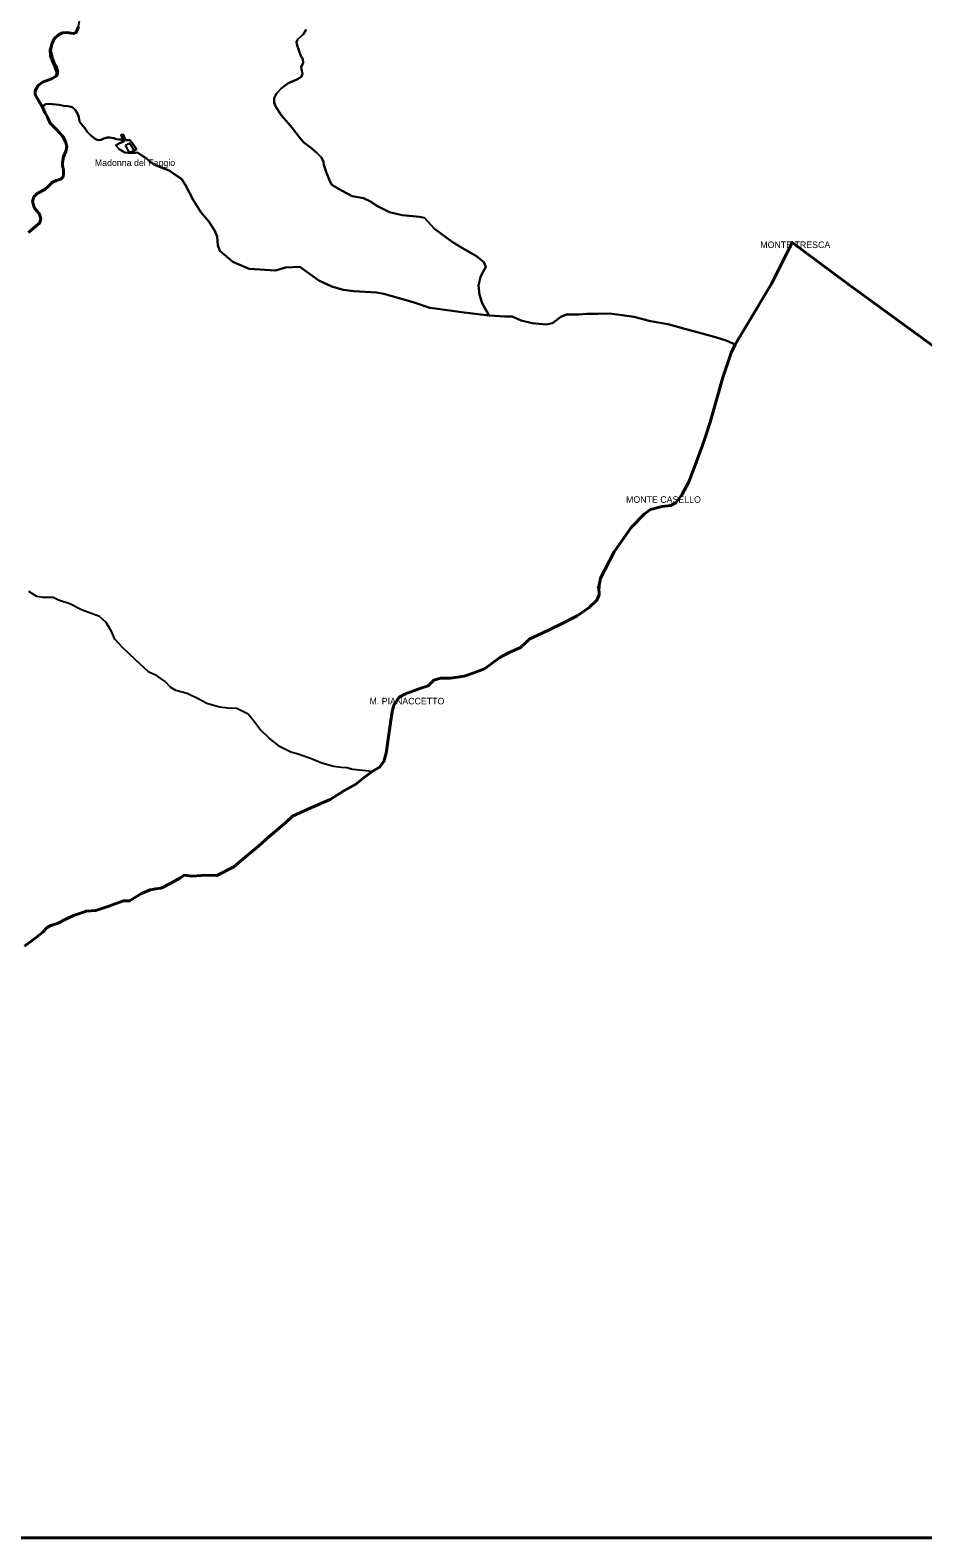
# Model space of a CAD drawing. Extents: x 645880 to 658994, y 884400 to 894744.
# Drawn here: x 651612 to 653916, y 884400 to 888292 of the extents above; entities that cross this region are included whole.
import ezdxf
from ezdxf.enums import TextEntityAlignment as Align

# ---------------------------------------------------------------- set-up
doc = ezdxf.new("R2010")
doc.units = 0
doc.header["$LTSCALE"] = 10
doc.header["$PDMODE"] = 32
doc.header["$PDSIZE"] = 5
for name, color, linetype, lineweight in [('18', 7, 'Continuous', 25), ('2', 7, 'Continuous', 25), ('59', 7, 'Continuous', 40), ('63', 7, 'Continuous', 35)]:
    doc.layers.add(name, color=color, linetype=linetype, lineweight=lineweight)
doc.layers.add('60', color=7, linetype='Continuous')

msp = doc.modelspace()

# ---------------------------------------------------------------- linework, layer by layer
at = {"layer": '18'}
for points in [[(651679.17, 888183.52), (651674.63, 888197.73), (651669.19, 888209.23), (651662.85, 888224.95), (651661.94, 888240.68), (651667.38, 888257.32), (651673.26, 888269.69), (651684.33, 888280.01), (651694.98, 888284.97), (651706.48, 888285.38), (651723.65, 888283.39), (651732.07, 888285.72), (651736.28, 888300.67), (651739, 888316.08), (651740.59, 888333.89), (651738.85, 888344.08), (651731.18, 888352.01), (651709.04, 888367.7), (651694.13, 888390.42), (651681.78, 888411.08), (651676.25, 888430.49), (651676.86, 888459.65)], [(653430.75, 887480.32), (653408.36, 887490.26), (653383.29, 887498.33), (653345.76, 887508.94), (653310.84, 887517.91), (653257, 887532.38), (653212.48, 887540.2), (653169.23, 887552.1), (653133.87, 887556.72), (653107.94, 887560.26), (653077.67, 887559.48), (653048, 887559.68), (653026.97, 887557.91), (653011.45, 887557.89), (652995.93, 887557.49), (652981.58, 887551.4), (652959.57, 887535.08), (652943.26, 887532.32), (652907.3, 887535.67), (652878.61, 887541.96), (652855.62, 887552.58), (652836.36, 887552.38), (652796.08, 887555.13), (652787.7, 887570.02), (652777.81, 887586.99), (652771.32, 887608.23), (652768.96, 887632.22), (652773.68, 887655.03), (652782.52, 887670.96), (652787.63, 887680.79), (652782.52, 887692.39), (652763.26, 887708.71), (652727.3, 887729.16), (652700.82, 887745.68), (652654.8, 887778.72), (652629.45, 887806.84), (652616.48, 887809.59), (652571.85, 887813.8), (652538.72, 887821.86), (652508.27, 887837.1), (652488.56, 887850.54), (652471.55, 887857.71), (652442.96, 887862.87), (652429.79, 887869.75), (652407.06, 887881.91), (652389.71, 887893.34), (652382.88, 887906.11), (652376.55, 887923.23), (652369.44, 887943.75), (652368.49, 887952.13), (652363.77, 887963.15), (652351.55, 887975.33), (652334.07, 887989.32), (652318.19, 888001.49), (652307.18, 888013.88), (652287.44, 888039.34), (652277.82, 888051.58), (652260.34, 888071.7), (652245.48, 888093.57), (652241.11, 888104.94), (652240.96, 888116.34), (652247.25, 888128.33), (652260.62, 888142.1), (652279.09, 888155.67), (652290.68, 888159.8), (652303.65, 888165.89), (652311.51, 888172.18), (652314.66, 888179.85), (652312.69, 888186.93), (652310.92, 888196.37), (652316.03, 888207.19), (652315.13, 888216.88), (652309.29, 888227.39), (652299.92, 888255.17), (652299.33, 888261.86), (652302.28, 888268.74), (652317.21, 888281.72), (652323.7, 888293.52)], [(652323.7, 888293.52), (652317.21, 888281.72), (652302.28, 888268.74), (652299.33, 888261.86), (652299.92, 888255.17), (652309.29, 888227.39), (652315.13, 888216.88), (652316.03, 888207.19), (652310.92, 888196.37), (652312.69, 888186.93), (652314.66, 888179.85), (652311.51, 888172.18), (652303.65, 888165.89), (652290.68, 888159.8), (652279.09, 888155.67), (652260.62, 888142.1), (652247.25, 888128.33), (652240.96, 888116.34), (652241.11, 888104.94)], [(651853.69, 888004.63), (651847.22, 888009.53), (651840.4, 888009.53), (651834.67, 888010.08), (651826.76, 888013.08), (651816.94, 888014.99), (651810.12, 888014.45), (651801.67, 888012.26), (651795.12, 888008.71), (651788.85, 888007.62), (651785.03, 888008.17), (651780.39, 888010.08), (651767.03, 888020.45), (651759.39, 888028.09), (651752.57, 888038.74), (651744.12, 888048.84), (651738.66, 888056.21), (651736.75, 888066.86), (651733.48, 888076.41), (651727.48, 888085.97), (651722.57, 888091.15), (651717.66, 888093.88), (651708.93, 888095.79), (651697.74, 888096.61), (651686.01, 888098.52), (651668.56, 888100.43), (651658.46, 888101.8), (651652.19, 888100.44), (651645.1, 888096.35), (651640.78, 888095.21), (651635.03, 888106.1), (651624.16, 888124.57), (651623.65, 888127), (651624.76, 888139.66), (651632.32, 888150.55), (651643.01, 888157.31), (651666.43, 888166.4), (651677.05, 888172.63), (651679.47, 888176.86), (651679.17, 888183.52)], [(651640.78, 888095.21), (651645.1, 888096.35), (651652.19, 888100.44), (651658.46, 888101.8), (651668.56, 888100.43), (651686.01, 888098.52), (651697.74, 888096.61), (651708.93, 888095.79), (651717.66, 888093.88), (651722.57, 888091.15), (651727.48, 888085.97), (651733.48, 888076.41), (651736.75, 888066.86), (651738.66, 888056.21), (651744.12, 888048.84), (651752.57, 888038.74), (651759.39, 888028.09), (651767.03, 888020.45), (651780.39, 888010.08), (651785.03, 888008.17), (651788.85, 888007.62), (651795.12, 888008.71), (651801.67, 888012.26), (651810.12, 888014.45), (651816.94, 888014.99), (651826.76, 888013.08), (651834.67, 888010.08), (651840.4, 888009.53), (651847.22, 888009.53), (651853.69, 888004.63)], [(651649.85, 888079.07), (651643.12, 888091.05), (651640.78, 888095.21)], [(651680.1, 888034.48), (651662.24, 888051.05), (651657.1, 888062.54), (651649.85, 888079.07)], [(652241.11, 888104.94), (652245.48, 888093.57), (652260.34, 888071.7), (652277.82, 888051.58), (652287.44, 888039.34), (652307.18, 888013.88), (652318.19, 888001.49), (652334.07, 887989.32), (652351.55, 887975.33), (652363.77, 887963.15), (652368.49, 887952.13), (652369.44, 887943.75), (652376.55, 887923.23), (652382.88, 887906.11), (652389.71, 887893.34), (652407.06, 887881.91), (652429.79, 887869.75), (652442.96, 887862.87), (652471.55, 887857.71), (652488.56, 887850.54), (652508.27, 887837.1), (652538.72, 887821.86), (652571.85, 887813.8), (652616.48, 887809.59), (652629.45, 887806.84), (652654.8, 887778.72), (652700.82, 887745.68), (652727.3, 887729.16), (652763.26, 887708.71), (652782.52, 887692.39), (652787.63, 887680.79), (652782.52, 887670.96), (652773.68, 887655.03), (652768.96, 887632.22), (652771.32, 887608.23), (652777.81, 887586.99), (652787.7, 887570.02), (652796.08, 887555.13)], [(651695.83, 888017.52), (651680.1, 888034.48), (651680.08, 888034.46)], [(651697.99, 887931.05), (651694.98, 887941.76), (651694.97, 887950.18), (651697.95, 887964.64), (651703.92, 887978.69), (651706.47, 887990.25), (651704.85, 887999.03), (651695.83, 888017.52), (651695.86, 888017.55)], [(651853.69, 888004.63), (651841.96, 888000.28), (651832.94, 887994.35), (651841.19, 887984.62), (651855.96, 887976.03), (651871.85, 887974.41)], [(651871.85, 887974.41), (651885.69, 887984.62), (651877.19, 887997.63), (651868.69, 888007.63), (651857.19, 888007.63), (651851.69, 888022.64), (651846.19, 888021.14), (651853.69, 888004.63)], [(652796.08, 887555.13), (652724.68, 887563.5), (652663.58, 887572.55), (652643.21, 887574.82), (652600.27, 887589.57), (652524.79, 887611.05), (652505.18, 887614.82), (652447.03, 887617.71), (652419.19, 887621.61), (652389.77, 887629.92), (652356.58, 887645.77), (652307.55, 887680.49), (652270.6, 887678.98), (652244.59, 887671.17), (652177.06, 887675.2), (652134.93, 887693.68), (652101.19, 887721.82), (652096.35, 887737.1), (652094.09, 887758.99), (652088.06, 887774.09), (652073.07, 887797.79), (652051.98, 887821.7), (652032.3, 887854.06), (652012.63, 887891.83), (652002.07, 887907.68), (651982.57, 887921.05), (651970.27, 887929.14), (651949.88, 887936.87), (651935.47, 887943.56), (651923.52, 887949.89), (651911.57, 887960.44), (651897.51, 887969.58), (651888.38, 887975.91), (651883.46, 887975.21), (651871.85, 887974.41)], [(651871.85, 887974.41), (651883.46, 887975.21), (651888.38, 887975.91), (651897.51, 887969.58), (651911.57, 887960.44), (651923.52, 887949.89), (651935.47, 887943.56), (651949.88, 887936.87), (651970.27, 887929.14), (651982.57, 887921.05), (652002.07, 887907.68), (652012.63, 887891.83), (652032.3, 887854.06), (652051.98, 887821.7), (652073.07, 887797.79), (652088.06, 887774.09), (652094.09, 887758.99), (652096.35, 887737.1), (652101.19, 887721.82), (652134.93, 887693.68), (652177.06, 887675.2), (652244.59, 887671.17), (652270.6, 887678.98), (652307.55, 887680.49), (652356.58, 887645.77), (652389.77, 887629.92), (652419.19, 887621.61), (652447.03, 887617.71), (652505.18, 887614.82), (652524.79, 887611.05), (652600.27, 887589.57), (652643.21, 887574.82), (652663.58, 887572.55), (652724.68, 887563.5), (652796.08, 887555.13), (652836.36, 887552.38), (652855.62, 887552.58), (652878.61, 887541.96), (652907.3, 887535.67), (652943.26, 887532.32)], [(651697.96, 887920.28), (651697.99, 887931.05), (651697.96, 887931.02)], [(651621.31, 887861.21), (651623.69, 887864.7), (651629.4, 887870.3), (651649.84, 887880.21), (651659.21, 887888.88), (651668.58, 887898.8), (651678.8, 887903.76), (651690.29, 887907.06), (651696.68, 887912.84), (651697.96, 887920.28), (651697.99, 887920.31)], [(651617.91, 887849.64), (651618.66, 887855.46), (651621.31, 887861.21)], [(651622.59, 887832.29), (651619.29, 887839.73), (651617.91, 887849.64)], [(651638.77, 887805.44), (651637.53, 887813.5), (651634.51, 887818.66), (651622.59, 887832.29)], [(651607.34, 887769.35), (651626, 887785.62), (651636.21, 887794.7)], [(651636.21, 887794.7), (651638.58, 887800.08), (651638.77, 887805.44)], [(653984.94, 887445.15), (653578.53, 887743.64), (653524.99, 887636.78), (653462.47, 887532.18), (653430.75, 887480.32)], [(652943.26, 887532.32), (652959.57, 887535.08), (652981.58, 887551.4), (652995.93, 887557.49), (653011.45, 887557.89), (653026.97, 887557.91), (653048, 887559.68), (653077.67, 887559.48), (653107.94, 887560.26), (653133.87, 887556.72), (653169.23, 887552.1), (653212.48, 887540.2), (653257, 887532.38), (653310.84, 887517.91), (653345.76, 887508.94), (653383.29, 887498.33), (653408.36, 887490.26), (653430.75, 887480.32), (653420.79, 887458.34), (653399.04, 887395.05), (653366.42, 887279.9), (653354.6, 887242.97), (653328.2, 887168.62), (653311.17, 887125.66), (653293.29, 887091.79), (653277.96, 887071.96), (653263.86, 887064.99), (653242.57, 887061.69), (653212.77, 887054.25), (653197.44, 887043.51), (653162.52, 887007.99), (653119.09, 886945.2), (653083.32, 886877.46), (653079.06, 886853.5)], [(652494.68, 886378.42), (652444.74, 886382.77), (652428.67, 886387.16), (652414.07, 886388.62), (652394.35, 886390.81), (652361.49, 886400.31), (652343.96, 886408.35), (652332.28, 886412), (652303.07, 886422.97), (652284.08, 886428.08), (652257.06, 886441.96), (652228.58, 886463.89), (652204.48, 886487.27), (652186.23, 886511.39), (652174.54, 886526), (652157.02, 886534.77), (652144.6, 886540.62), (652121.96, 886541.35), (652100.38, 886543.86), (652067.63, 886553.49), (652048.37, 886564.09), (652016.6, 886579.51), (651987.71, 886587.22), (651974.22, 886594.93), (651959.78, 886610.35), (651937.63, 886625.77), (651917.41, 886634.44), (651882.74, 886667.2), (651850.96, 886697.08), (651829.78, 886719.24), (651821.11, 886739.48), (651807.63, 886762.6), (651790.3, 886778.02), (651773.92, 886783.8), (651744.07, 886795.37), (651714.22, 886810.79), (651684.37, 886820.42), (651670.88, 886827.17), (651644.88, 886827.17), (651628.51, 886830.06), (651608.29, 886842.59)], [(652494.68, 886378.42), (652444.74, 886382.77), (652428.67, 886387.16), (652414.07, 886388.62), (652394.35, 886390.81), (652361.49, 886400.31), (652343.96, 886408.35), (652332.28, 886412), (652303.07, 886422.97), (652284.08, 886428.08), (652257.06, 886441.96), (652228.58, 886463.89), (652204.48, 886487.27), (652186.23, 886511.39), (652174.54, 886526), (652157.02, 886534.77), (652144.6, 886540.62), (652121.96, 886541.35), (652100.38, 886543.86), (652067.63, 886553.49), (652048.37, 886564.09), (652016.6, 886579.51), (651987.71, 886587.22), (651974.22, 886594.93), (651959.78, 886610.35), (651937.63, 886625.77), (651917.41, 886634.44), (651882.74, 886667.2), (651850.96, 886697.08), (651829.78, 886719.24), (651821.11, 886739.48), (651807.63, 886762.6), (651790.3, 886778.02), (651773.92, 886783.8), (651744.07, 886795.37), (651714.22, 886810.79), (651684.37, 886820.42), (651670.88, 886827.17), (651644.88, 886827.17), (651628.51, 886830.06), (651608.29, 886842.59)], [(653079.06, 886853.5), (653079.91, 886833.67), (653073.95, 886820.45), (653054.37, 886801.45), (653023.71, 886779.97), (652979.42, 886757.66), (652930.88, 886734.53), (652901.42, 886720.76), (652876.73, 886698.45), (652823.93, 886672.02), (652783.9, 886643.1), (652756.65, 886632.36), (652731.95, 886624.1), (652696.18, 886619.14), (652670.64, 886619.14), (652653.6, 886614.19), (652639.13, 886599.32), (652616.98, 886591.88), (652580.36, 886578.66), (652564.18, 886569.57), (652550.56, 886548.92), (652546.3, 886533.22), (652541.52, 886504), (652530.45, 886425.51), (652524.49, 886404.03), (652513.42, 886389.16), (652494.68, 886378.42)], [(652093.13, 886109.37), (652137.41, 886131.67), (652166.81, 886157.02), (652200.87, 886185.11), (652227.27, 886209.06), (652249.41, 886227.24), (652271.56, 886246.24), (652288.59, 886262.76), (652336.28, 886284.24), (652385.67, 886305.72), (652421.44, 886328.03), (652452.1, 886345.38), (652473.39, 886362.73), (652494.68, 886378.42)], [(651597.09, 885926.98), (651623.49, 885946.81), (651643.93, 885963.33), (651655.85, 885974.9), (651683.95, 885986.46), (651723.53, 886006.1), (651756.74, 886017.66), (651781.44, 886019.32), (651812.1, 886029.23), (651852.12, 886044.1), (651868.3, 886044.1), (651898.96, 886063.1), (651921.1, 886072.19), (651935.58, 886075.49), (651950.06, 886077.15), (651974.75, 886089.54), (651999.45, 886103.58), (652008.82, 886110.19), (652029.26, 886107.71), (652053.1, 886109.37), (652085.46, 886110.19), (652093.13, 886109.37)]]:
    msp.add_lwpolyline(points, dxfattribs=at)
msp.add_point((653079.06, 886853.5), dxfattribs=at)
at = {"layer": '2'}
for points in [[(651846.19, 888021.14), (651851.69, 888022.64), (651857.19, 888007.63), (651868.69, 888007.63), (651877.19, 887997.63), (651885.69, 887984.62), (651871.85, 887974.41), (651855.96, 887976.03), (651841.19, 887984.62), (651832.94, 887994.35)], [(651832.94, 887994.35), (651841.96, 888000.28), (651853.69, 888004.63), (651846.19, 888021.14)], [(651857.38, 887994.64), (651867.78, 888000.3), (651879.26, 887982.6)], [(651879.26, 887982.6), (651871.97, 887976.58), (651867.41, 887976.4), (651857.38, 887994.64)]]:
    msp.add_lwpolyline(points, dxfattribs=at)
at = {"layer": '59'}
for points in [[(651677.49, 888200.26), (651673.66, 888207.28), (651668.55, 888220.91), (651663.87, 888239.5), (651667.7, 888255.61), (651673.23, 888269.66), (651684.3, 888279.98), (651694.95, 888284.94), (651706.45, 888285.35), (651723.48, 888283.29), (651730.29, 888285.76), (651736.25, 888300.64)], [(651607.34, 887769.35), (651626, 887785.62), (651636.21, 887794.7), (651638.77, 887805.44), (651634.51, 887818.66), (651622.59, 887832.29), (651617.91, 887849.64), (651621.31, 887861.21), (651629.4, 887870.3), (651649.84, 887880.21), (651659.21, 887888.88), (651668.58, 887898.8), (651678.8, 887903.76), (651690.29, 887907.06), (651696.68, 887912.84), (651697.96, 887920.28), (651697.96, 887931.02), (651694.98, 887941.76), (651694.97, 887950.18), (651697.95, 887964.64), (651703.92, 887978.69), (651706.47, 887990.25), (651702.64, 888003.88), (651695.83, 888017.52), (651680.07, 888034.45), (651671.13, 888043.54), (651663.04, 888051.8), (651657.93, 888064.61), (651649.84, 888079.06), (651641.32, 888097.24), (651629.83, 888115.83), (651625.14, 888124.09), (651624.29, 888128.63), (651624.26, 888134.58), (651631.08, 888147.8), (651643, 888157.3), (651666.42, 888166.39), (651680.05, 888173.82), (651682.6, 888184.15), (651677.49, 888200.26)], [(653984.94, 887445.15), (653715.82, 887641.18), (653578.53, 887743.64), (653524.99, 887636.78), (653462.47, 887532.18), (653430.75, 887480.32)], [(653430.75, 887480.32), (653420.79, 887458.34), (653399.04, 887395.05), (653366.42, 887279.9), (653354.6, 887242.97), (653345.24, 887214.88), (653328.2, 887168.62), (653311.17, 887125.66), (653293.29, 887091.79), (653277.96, 887071.96), (653263.86, 887064.99), (653242.57, 887061.69), (653212.77, 887054.25), (653197.44, 887043.51), (653162.52, 887007.99), (653119.09, 886945.2), (653083.32, 886877.46), (653079.06, 886853.5), (653079.91, 886833.67), (653073.95, 886820.45), (653054.37, 886801.45), (653023.71, 886779.97), (652979.42, 886757.66), (652930.88, 886734.53), (652901.42, 886720.76), (652876.73, 886698.45), (652846.07, 886684.41), (652823.93, 886672.02), (652783.9, 886643.1), (652756.65, 886632.36), (652731.95, 886624.1), (652696.18, 886619.14), (652670.64, 886619.14), (652653.6, 886614.19), (652639.13, 886599.32), (652616.98, 886591.88), (652580.36, 886578.66), (652564.18, 886569.57), (652550.56, 886548.92), (652546.3, 886533.22)], [(652546.3, 886533.22), (652541.52, 886504), (652530.45, 886425.51), (652524.49, 886404.03), (652513.42, 886389.16), (652494.68, 886378.42), (652473.39, 886362.73), (652452.1, 886345.38), (652421.44, 886328.03), (652385.67, 886305.72), (652336.28, 886284.24), (652288.59, 886262.76), (652271.56, 886246.24), (652249.41, 886227.24), (652227.27, 886209.06), (652200.87, 886185.11), (652166.81, 886157.02), (652137.41, 886131.67), (652093.13, 886109.37), (652085.46, 886110.19), (652053.1, 886109.37), (652029.26, 886107.71), (652008.82, 886110.19), (651999.45, 886103.58), (651974.75, 886089.54), (651950.06, 886077.15), (651935.58, 886075.49), (651921.1, 886072.19), (651898.96, 886063.1), (651868.3, 886044.1), (651852.12, 886044.1), (651812.1, 886029.23), (651781.44, 886019.32), (651756.74, 886017.66), (651723.53, 886006.1), (651703.54, 885997.2), (651683.95, 885986.46), (651665.22, 885980.68), (651655.85, 885974.9), (651643.93, 885963.33)], [(651643.93, 885963.33), (651623.49, 885946.81), (651597.09, 885926.98)]]:
    msp.add_lwpolyline(points, dxfattribs=at)
at = {"layer": '63', "lineweight": 40}
msp.add_lwpolyline([(656397.82, 884399.72), (650080.32, 884399.72), (650080.32, 889588.16), (656397.82, 889588.16)], close=True, dxfattribs=at)

# ---------------------------------------------------------------- texts
at = {"layer": '60'}
for s, p in [('Madonna del Faggio', (651882.07, 887940.97)), ('MONTE TRESCA', (653586.3, 887729.16)), ('MONTE CASELLO', (653246.16, 887071.59)), ('M. PIANACCETTO', (652584.03, 886551.19))]:
    msp.add_text(s, height=17, dxfattribs=at).set_placement(p, align=Align.CENTER)

doc.saveas('drawing.dxf')
